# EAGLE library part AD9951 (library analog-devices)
14-bit DAC Direct Digital Synthesizer 400 MSPS 14-Bit, 1.8 V CMOS Source: http://www.analog.com/static/imported-files/data_sheets/AD9951.pdf
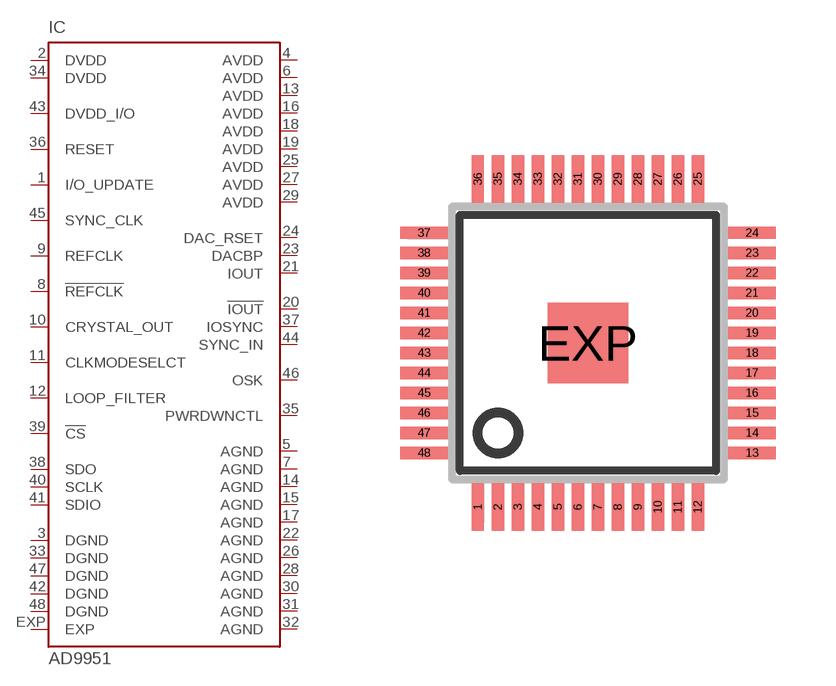
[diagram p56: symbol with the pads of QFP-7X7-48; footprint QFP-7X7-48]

Designator prefix IC

## AD9951EP (MPN: AD9951YSVZ; OC_FARNELL: 8398445; OC_NEWARK: 19M1019)  [QFP-7X7-48]
1  I/O_UPDATE  in
2  DVDD  pwr
3  DGND  pwr
4  AVDD  pwr
5  AGND  pwr
6  AVDD  pwr
7  AGND  pwr
8  !REFCLK  in
9  REFCLK  in
10  CRYSTAL_OUT  out
11  CLKMODESELCT  in
12  LOOP_FILTER  in
13  AVDD  pwr
14  AGND  pwr
15  AGND  pwr
16  AVDD  pwr
17  AGND  pwr
18  AVDD  pwr
19  AVDD  pwr
20  !IOUT  out
21  IOUT  out
22  AGND  pwr
23  DACBP  in
24  DAC_RSET  in
25  AVDD  pwr
26  AGND  pwr
27  AVDD  pwr
28  AGND  pwr
29  AVDD  pwr
30  AGND  pwr
31  AGND  pwr
32  AGND  pwr
33  DGND  pwr
34  DVDD  pwr
35  PWRDWNCTL  in
36  RESET  in
37  IOSYNC  in
38  SDO  in
39  !CS  in
40  SCLK  in
41  SDIO
42  DGND  pwr
43  DVDD_I/O  pwr
44  SYNC_IN  in
45  SYNC_CLK  out
46  OSK  in
47  DGND  pwr
48  DGND  pwr
EXP  EXP  pas

## Footprint QFP-7X7-48 (pad centres in mm)
TQFP48 7x7 Thin Plastic Quad Flat Package, Exposed Pad, TQFP/EP Source: www.analog.com/UploadedFiles/Data_Sheets/33830397585263AD9859_0.pdf
smd 0.3 x 1.2: 1 -2.75,-4.1; 2 -2.25,-4.1; 3 -1.75,-4.1; 4 -1.25,-4.1; 5 -0.75,-4.1; 6 -0.25,-4.1; 7 0.25,-4.1; 8 0.75,-4.1; 9 1.25,-4.1; 10 1.75,-4.1; 11 2.25,-4.1; 12 2.75,-4.1; 25 2.75,4.1; 26 2.25,4.1; 27 1.75,4.1; 28 1.25,4.1; 29 0.75,4.1; 30 0.25,4.1; 31 -0.25,4.1; 32 -0.75,4.1; 33 -1.25,4.1; 34 -1.75,4.1; 35 -2.25,4.1; 36 -2.75,4.1
smd 1.2 x 0.3: 13 4.1,-2.75; 14 4.1,-2.25; 15 4.1,-1.75; 16 4.1,-1.25; 17 4.1,-0.75; 18 4.1,-0.25; 19 4.1,0.25; 20 4.1,0.75; 21 4.1,1.25; 22 4.1,1.75; 23 4.1,2.25; 24 4.1,2.75; 37 -4.1,2.75; 38 -4.1,2.25; 39 -4.1,1.75; 40 -4.1,1.25; 41 -4.1,0.75; 42 -4.1,0.25; 43 -4.1,-0.25; 44 -4.1,-0.75; 45 -4.1,-1.25; 46 -4.1,-1.75; 47 -4.1,-2.25; 48 -4.1,-2.75
smd 2 x 2: EXP 0,0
